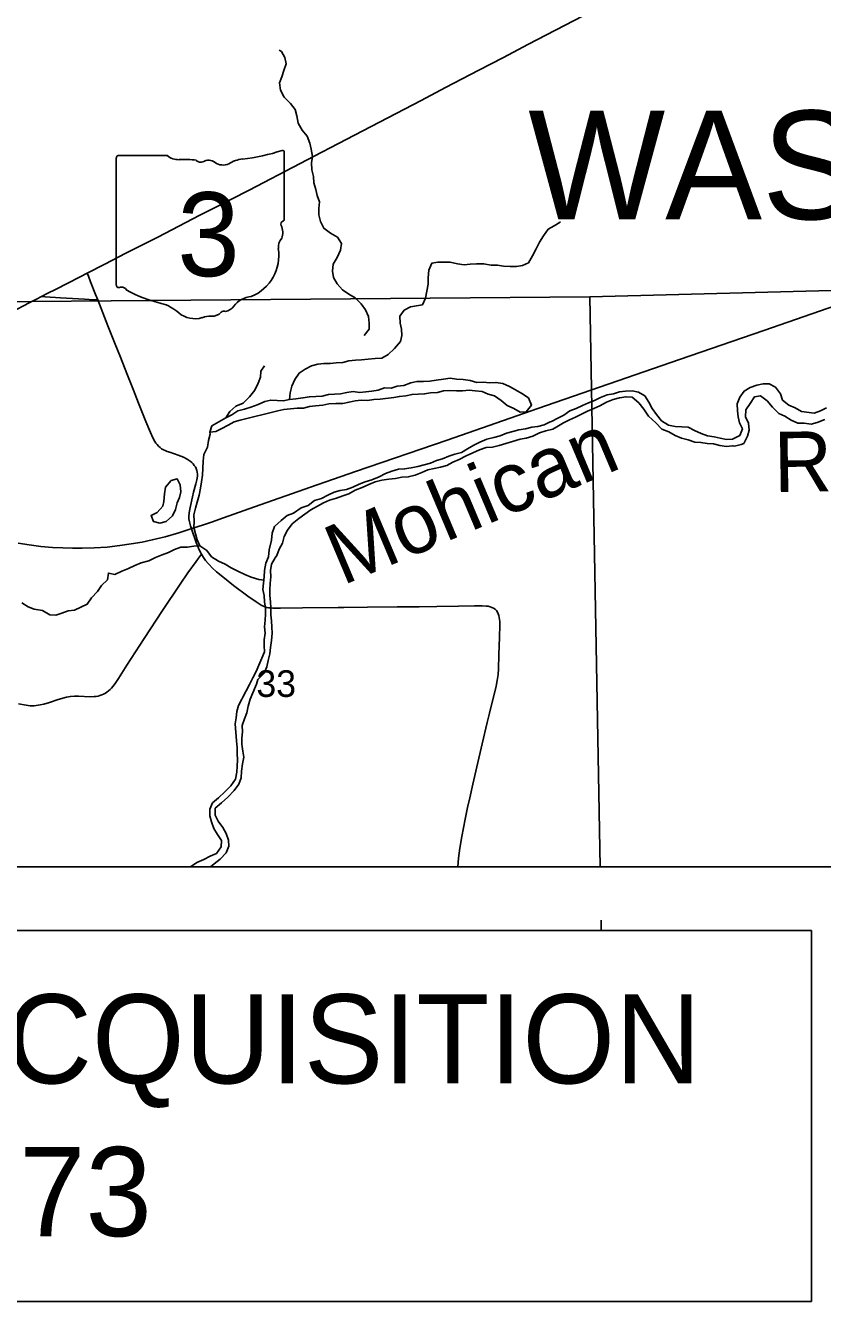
# Model space of a CAD drawing. Extents: x 0 to 34, y 0 to 22.
# Drawn here: x 6.214 to 7.465, y 16.167 to 18.172 of the extents above; entities that cross this region are included whole.
import ezdxf

# ---------------------------------------------------------------- set-up
doc = ezdxf.new("R2010")
doc.units = 0
for name, color, linetype in [('GM_X_County_Road', 7, 'Continuous'), ('GM_X_County_Road_Text', 7, 'Continuous'), ('GM_X_County_Text', 7, 'Continuous'), ('GM_X_Major_River', 7, 'Continuous'), ('GM_X_Major_River_Text', 7, 'Continuous'), ('GM_X_Minor_River_Text', 7, 'Continuous'), ('GM_X_State_Location', 7, 'Continuous'), ('GM_X_State_Route', 7, 'Continuous'), ('GM_X_State_Shield', 7, 'Continuous'), ('GM_X_Township_Road', 7, 'Continuous'), ('GM_X_Unincorporated_Location', 7, 'Continuous'), ('SH_Text', 7, 'Continuous')]:
    doc.layers.add(name, color=color, linetype=linetype)

msp = doc.modelspace()

# ---------------------------------------------------------------- linework, layer by layer
at = {"layer": 'GM_X_County_Road'}
for p, q in [((6.3562, 17.9642), (6.3562, 17.764)), ((6.436, 17.9676), (6.3588, 17.9676)), ((6.6199, 17.8679), (6.6199, 17.9726)), ((6.6199, 17.8679), (6.6199, 17.8679))]:
    msp.add_line(p, q, dxfattribs=at)
msp.add_lwpolyline([(6.1918, 17.7219), (6.2195, 17.7361), (6.2309, 17.742), (6.2388, 17.7461), (6.2489, 17.7513), (6.2608, 17.7575), (6.2995, 17.7773), (6.3105, 17.783), (6.3381, 17.7972), (6.3713, 17.8141), (6.4212, 17.8395), (6.4874, 17.8738), (6.5123, 17.8866), (6.5372, 17.8991), (6.5648, 17.9134), (6.6448, 17.955), (6.6668, 17.9665), (6.7053, 17.9867), (6.7301, 17.9997), (6.8348, 18.0543), (6.8733, 18.0745), (6.9256, 18.102), (6.9642, 18.122), (7.0028, 18.1422), (7.0896, 18.1872)], dxfattribs=at)
for centre, radius, start, end in [((6.3593, 17.9646), 0.00305, 98.1301, 188.1301), ((6.4544, 17.9908), 0.0296, 231.6195, 271.1119), ((6.4643, 17.8553), 0.1064, 80.4867, 94.9883), ((6.5616, 17.9065), 0.0563, 97.3462, 120.7689), ((6.526, 18.2404), 0.2796, 275.8445, 288.9065), ((6.617, 17.973), 0.00294, 351.8621, 97.738), ((6.4884, 17.9656), 0.00855, 219.7921, 297.1024), ((6.5009, 17.9425), 0.0178, 54.4667, 119.1411), ((6.5239, 17.9742), 0.0214, 233.8562, 294.8282), ((6.6192, 17.8602), 0.00454, 107.944, 210.337), ((6.6168, 17.8675), 0.00314, 289.6038, 7.7341), ((6.5903, 17.847), 0.0273, 340.033, 23.6496), ((6.5416, 17.8108), 0.0699, 292.3089, 8.9858), ((6.6304, 17.8241), 0.0198, 136.8065, 186.9296), ((6.3593, 17.7636), 0.00308, 171.9584, 258.3066), ((6.3597, 17.7841), 0.0235, 267.339, 280.6039), ((6.3646, 17.7525), 0.00848, 29.7484, 93.2717), ((6.4716, 17.9323), 0.2019, 240.4129, 257.1985), ((6.5711, 17.7079), 0.0383, 94.4031, 142.5768), ((6.4114, 17.6741), 0.0632, 47.1842, 75.836), ((6.5058, 17.7365), 0.0214, 268.777, 315.5493), ((6.5252, 17.7171), 0.00601, 65.7517, 132.6484), ((6.5226, 17.7446), 0.0226, 282.8732, 323.2771), ((6.4797, 17.7515), 0.0401, 230.7004, 286.2918), ((6.5029, 17.6823), 0.0329, 85.6951, 111.2099)]:
    msp.add_arc(centre, radius, start, end, dxfattribs=at)
at = {"layer": 'GM_X_County_Road_Text'}
for points in [[(6.7453, 17.685), (6.7533, 17.6948), (6.7534, 17.7042), (6.7524, 17.7149), (6.7475, 17.7252), (6.7408, 17.7347), (6.7314, 17.7443), (6.7216, 17.75), (6.7114, 17.7566), (6.7031, 17.7661), (6.6972, 17.776), (6.6957, 17.7859), (6.6966, 17.7969), (6.7031, 17.8075), (6.7085, 17.8192), (6.7097, 17.8294), (6.7037, 17.8393), (6.6924, 17.8459), (6.6823, 17.8535), (6.6767, 17.8642), (6.6741, 17.8745), (6.6742, 17.8847), (6.6754, 17.8949), (6.6717, 17.9048), (6.6695, 17.9143), (6.6662, 17.9246), (6.6659, 17.9348), (6.6633, 17.9451), (6.663, 17.9561), (6.6642, 17.966), (6.6624, 17.9777), (6.6602, 17.9872), (6.6558, 17.9979), (6.6479, 18.0078), (6.6416, 18.0185), (6.6398, 18.0299), (6.6372, 18.0398), (6.6297, 18.0493), (6.6199, 18.0593), (6.6143, 18.0703), (6.6125, 18.0817), (6.616, 18.0915), (6.6191, 18.1014), (6.623, 18.112), (6.6208, 18.1218), (6.6156, 18.1314), (6.6118, 18.1333)], [(6.6281, 17.5844), (6.6293, 17.595), (6.6321, 17.6052), (6.6367, 17.6158), (6.6432, 17.626), (6.6528, 17.632), (6.6626, 17.6372), (6.6725, 17.6397), (6.682, 17.6412), (6.6919, 17.6411), (6.7017, 17.6418), (6.712, 17.6424), (6.7215, 17.6454), (6.7317, 17.6464), (6.7412, 17.6467), (6.7518, 17.6478), (6.7628, 17.6488), (6.7734, 17.6495), (6.783, 17.6554), (6.7933, 17.6648), (6.8028, 17.6754), (6.8048, 17.6852), (6.8041, 17.6951), (6.8023, 17.7046), (6.8016, 17.7152), (6.8085, 17.725), (6.8181, 17.7302), (6.837, 17.7331), (6.8421, 17.7436), (6.8437, 17.7546), (6.846, 17.7656), (6.8461, 17.7758), (6.8473, 17.7876), (6.8516, 17.7985), (6.8611, 17.8), (6.871, 17.8003), (6.8808, 17.8002), (6.8922, 17.7978), (6.9024, 17.7962), (6.9119, 17.7972), (6.9217, 17.7975), (6.9331, 17.7978), (6.9452, 17.7954), (6.9547, 17.7953), (6.9645, 17.7941), (6.9747, 17.7933), (6.9846, 17.7935), (6.9941, 17.795), (7.0036, 17.7994), (7.0101, 17.81), (7.0159, 17.8209), (7.0209, 17.8315), (7.0271, 17.8417), (7.0344, 17.8519), (7.0439, 17.8571), (7.0534, 17.8631), (7.0519, 17.8627)], [(6.5282, 17.5557), (6.5343, 17.5655), (6.5439, 17.5742), (6.5553, 17.5786), (6.5656, 17.5888), (6.5736, 17.5989), (6.579, 17.6099), (6.5829, 17.6197), (6.583, 17.6292), (6.5891, 17.6375)], [(6.4875, 17.3544), (6.483, 17.3639), (6.4804, 17.3734), (6.4782, 17.3836), (6.4783, 17.3931), (6.478, 17.4034), (6.4804, 17.4136), (6.4831, 17.4234), (6.4862, 17.4344), (6.4882, 17.4454), (6.4898, 17.4552), (6.4914, 17.4654), (6.4919, 17.4768), (6.4927, 17.4878), (6.4936, 17.498), (6.4994, 17.5093), (6.501, 17.52), (6.5037, 17.5298), (6.503, 17.5332)], [(6.2078, 17.2651), (6.2176, 17.2586), (6.2274, 17.2551), (6.2403, 17.2531), (6.2516, 17.2461), (6.261, 17.2457), (6.2705, 17.2486), (6.2808, 17.2523), (6.2907, 17.2537), (6.3006, 17.2582), (6.3105, 17.263), (6.3174, 17.2728), (6.3265, 17.2826), (6.3327, 17.2924), (6.3422, 17.3011), (6.3438, 17.3117), (6.3541, 17.3097), (6.3651, 17.3149), (6.3754, 17.319), (6.3853, 17.3234), (6.3955, 17.3279), (6.4073, 17.3312), (6.4176, 17.3364), (6.4282, 17.3405), (6.4381, 17.3442), (6.4476, 17.3486), (6.4575, 17.3527), (6.4677, 17.3523), (6.478, 17.3541), (6.4875, 17.3544), (6.4984, 17.347), (6.5055, 17.3375), (6.5165, 17.3306), (6.527, 17.3256), (6.5368, 17.3202), (6.547, 17.3148), (6.558, 17.3097), (6.5682, 17.3055), (6.5803, 17.3016), (6.5882, 17.3007)]]:
    msp.add_lwpolyline(points, dxfattribs=at)
at = {"layer": 'GM_X_County_Text'}
msp.add_lwpolyline([(6.202, 17.3585), (6.2191, 17.356), (6.2374, 17.3536), (6.2559, 17.3519), (6.2721, 17.3512), (6.2873, 17.3507), (6.3024, 17.3508), (6.3216, 17.3513), (6.3419, 17.3527), (6.3619, 17.355), (6.3793, 17.3575), (6.3967, 17.3605), (6.4127, 17.3639), (6.4327, 17.3687), (6.4546, 17.3751), (6.4748, 17.3816), (6.493, 17.3873), (6.5055, 17.3919), (6.5244, 17.3984), (6.5733, 17.4156), (6.6611, 17.4466), (6.7321, 17.4713), (6.8757, 17.5205), (7.0185, 17.5701), (7.2408, 17.6471), (7.373, 17.6931), (7.8394, 17.8546)], dxfattribs=at)
at = {"layer": 'GM_X_Minor_River_Text'}
for points in [[(6.7919, 17.5875), (6.801, 17.5893), (6.8108, 17.59), (6.8207, 17.5925), (6.8302, 17.5928), (6.8404, 17.5931), (6.8499, 17.5949), (6.8605, 17.5952), (6.87, 17.5981), (6.8803, 17.5984), (6.8905, 17.5983), (6.9, 17.5979), (6.9102, 17.5989), (6.9201, 17.5981), (6.9307, 17.5968), (6.9405, 17.593), (6.9503, 17.5902), (6.9605, 17.5829), (6.9703, 17.5752), (6.9805, 17.5702), (6.9907, 17.5648), (7.0001, 17.5651), (7.0082, 17.5757), (7.0034, 17.5871), (6.9932, 17.594), (6.9834, 17.5998), (6.9736, 17.6048), (6.9634, 17.6094), (6.9524, 17.6114), (6.9425, 17.6108), (6.9327, 17.6116), (6.9224, 17.6113), (6.9119, 17.6141), (6.9009, 17.6157), (6.8907, 17.6165), (6.8804, 17.6178), (6.8702, 17.6163), (6.8588, 17.6146), (6.8489, 17.6135), (6.8387, 17.6125), (6.8281, 17.6126), (6.8186, 17.6104), (6.8079, 17.6067), (6.7973, 17.6052), (6.7878, 17.6023), (6.7776, 17.6028), (6.7677, 17.5991), (6.7575, 17.5976), (6.748, 17.5966), (6.7381, 17.5955), (6.7283, 17.5968), (6.7184, 17.5953), (6.7085, 17.5935), (6.6896, 17.5922), (6.6793, 17.5896), (6.6698, 17.5893), (6.6596, 17.5887), (6.6493, 17.5869), (6.638, 17.5855), (6.6281, 17.5844), (6.6182, 17.5826), (6.6088, 17.5827), (6.5989, 17.5835), (6.5894, 17.5813), (6.5788, 17.5765), (6.5677, 17.5724), (6.5575, 17.5691), (6.5472, 17.5666), (6.5377, 17.5606), (6.5282, 17.5557), (6.5061, 17.543), (6.503, 17.5332), (6.5125, 17.5343), (6.522, 17.5387), (6.5319, 17.5443), (6.5414, 17.5495), (6.5509, 17.5521)], [(6.5509, 17.5521), (6.6098, 17.5664), (6.6193, 17.5686), (6.6299, 17.5696), (6.6401, 17.571), (6.65, 17.5709), (6.6595, 17.5735), (6.669, 17.5746), (6.6807, 17.5756), (6.6902, 17.5774), (6.7008, 17.5784), (6.7118, 17.5783), (6.7217, 17.5805), (6.7312, 17.5823), (6.741, 17.5834), (6.7509, 17.5829), (6.7608, 17.5843), (6.7706, 17.585), (6.7919, 17.5875)], [(6.4557, 17.4307), (6.4578, 17.4392), (6.4564, 17.4502), (6.452, 17.4597), (6.4425, 17.4572), (6.4333, 17.4466), (6.4317, 17.4364), (6.4309, 17.4241)], [(6.4309, 17.4241), (6.4292, 17.4171), (6.4204, 17.4069), (6.4109, 17.4024), (6.4146, 17.3929), (6.4245, 17.3902), (6.4347, 17.3928), (6.4447, 17.4018), (6.4493, 17.4116), (6.452, 17.4222), (6.4557, 17.4307)]]:
    msp.add_lwpolyline(points, dxfattribs=at)
at = {"layer": 'GM_X_State_Route'}
msp.add_line((7.1178, 16.7504), (7.1176, 16.7664), dxfattribs=at)
for points in [[(7.1161, 16.8504), (7.0999, 17.7456), (8.0984, 17.7721), (8.1109, 16.7736), (7.5483, 16.7695)], [(6.0967, 17.7375), (7.0999, 17.7456), (7.1161, 16.8504)]]:
    msp.add_lwpolyline(points, dxfattribs=at)
at = {"layer": 'GM_X_State_Shield'}
for points in [[(7.4717, 17.5715), (7.4622, 17.5666), (7.4523, 17.5629), (7.4326, 17.5654), (7.4224, 17.5715), (7.4126, 17.5754), (7.4024, 17.5835), (7.3995, 17.5934), (7.3916, 17.6037), (7.3814, 17.6091), (7.372, 17.6088), (7.3625, 17.607), (7.3518, 17.6033), (7.3423, 17.5977), (7.3354, 17.5879), (7.3315, 17.5777), (7.3318, 17.5667), (7.3329, 17.5572), (7.3351, 17.5477), (7.3395, 17.5382), (7.3353, 17.528), (7.3242, 17.522), (7.3148, 17.5217), (7.3049, 17.5237), (7.2951, 17.526), (7.2849, 17.5273), (7.275, 17.5312), (7.2645, 17.5358), (7.2543, 17.5408), (7.2444, 17.5417), (7.2342, 17.5421), (7.2236, 17.5441), (7.2123, 17.5511), (7.2048, 17.561), (7.198, 17.5705), (7.1924, 17.5804), (7.1861, 17.59), (7.1763, 17.5958), (7.1664, 17.5981), (7.1562, 17.5975), (7.1467, 17.5964), (7.1372, 17.5935), (7.1273, 17.592), (7.1167, 17.5876), (7.1072, 17.5831), (7.0977, 17.5794), (7.0882, 17.5749), (7.0786, 17.5701), (7.0688, 17.5664), (7.0592, 17.5596), (7.0497, 17.5552), (7.0398, 17.55)], [(7.0481, 17.5415), (7.0584, 17.5479), (7.0679, 17.5524), (7.0774, 17.5565), (7.0964, 17.5661), (7.1063, 17.5702), (7.1158, 17.5743), (7.1261, 17.5803), (7.1364, 17.5847), (7.1463, 17.5869), (7.1569, 17.5887), (7.1667, 17.5883), (7.1769, 17.5791), (7.1848, 17.5695), (7.1919, 17.5581), (7.2035, 17.5477), (7.2129, 17.5378), (7.2239, 17.5335), (7.2341, 17.5281), (7.2439, 17.5238), (7.2545, 17.5211), (7.2651, 17.5172), (7.2745, 17.5171), (7.2844, 17.5151), (7.2942, 17.5147), (7.3041, 17.5123), (7.3147, 17.5107), (7.3242, 17.5114), (7.3253, 17.5117)], [(7.3374, 17.5139), (7.3416, 17.5154), (7.3478, 17.5267), (7.3501, 17.5365), (7.3491, 17.5475), (7.3442, 17.5571), (7.3451, 17.5681), (7.352, 17.5782), (7.3585, 17.5884), (7.368, 17.5902), (7.3786, 17.5825)], [(7.3786, 17.5825), (7.3868, 17.5722), (7.3966, 17.5627), (7.4064, 17.5584), (7.4162, 17.5522), (7.4268, 17.5472), (7.4366, 17.5471), (7.4476, 17.5455), (7.4571, 17.5485), (7.4693, 17.5529)], [(7.0398, 17.55), (7.0375, 17.5496), (7.028, 17.5448), (7.0185, 17.5422), (7.009, 17.5408), (6.9988, 17.5382), (6.9885, 17.5368), (6.979, 17.5342), (6.9692, 17.5316), (6.9589, 17.5276), (6.9494, 17.525), (6.9384, 17.5221), (6.9274, 17.5176), (6.9175, 17.5128), (6.9079, 17.5072), (6.8984, 17.5012), (6.8878, 17.4986), (6.8783, 17.4953), (6.8688, 17.4912), (6.8593, 17.4886), (6.8498, 17.4846), (6.8399, 17.482), (6.8296, 17.4794), (6.8194, 17.4772), (6.8091, 17.4754), (6.7993, 17.4748), (6.789, 17.4718), (6.7791, 17.4681), (6.7689, 17.4629), (6.7578, 17.4585), (6.7472, 17.4552), (6.7377, 17.4514), (6.7278, 17.4466), (6.7175, 17.4433), (6.7076, 17.4415), (6.6982, 17.4389), (6.6886, 17.4344), (6.6784, 17.4288), (6.6677, 17.4259), (6.6574, 17.418), (6.6464, 17.4143), (6.6346, 17.4057), (6.6247, 17.402), (6.6152, 17.3945), (6.6048, 17.3848), (6.601, 17.3746), (6.6001, 17.3636)], [(6.6083, 17.3392), (6.6121, 17.3491), (6.6171, 17.3589), (6.6199, 17.3691), (6.6249, 17.3793), (6.6325, 17.3891), (6.6429, 17.3977), (6.6524, 17.4041), (6.6619, 17.4112), (6.6722, 17.4168), (6.6817, 17.422), (6.6912, 17.4261), (6.7022, 17.4294), (6.7121, 17.4331), (6.7216, 17.436), (6.7315, 17.442), (6.7422, 17.4461), (6.7528, 17.4509), (6.7627, 17.455), (6.773, 17.4576), (6.784, 17.4594), (6.7946, 17.4604), (6.8045, 17.4622), (6.8147, 17.4629), (6.8257, 17.4654), (6.836, 17.4699), (6.8455, 17.474), (6.8554, 17.4758), (6.8656, 17.4783), (6.8755, 17.4805), (6.885, 17.4861), (6.8949, 17.4902), (6.9056, 17.4958), (6.9162, 17.5006), (6.9265, 17.5055), (6.9371, 17.5088), (6.947, 17.5095), (6.9576, 17.5124), (6.9679, 17.5153), (6.9785, 17.5187), (6.9903, 17.522), (6.9998, 17.5238), (7.0104, 17.5271), (7.0207, 17.5319), (7.031, 17.5353), (7.042, 17.5378), (7.0481, 17.5415)], [(7.3253, 17.5117), (7.3272, 17.5113), (7.3374, 17.5139)], [(6.6001, 17.3636), (6.5962, 17.3484), (6.5954, 17.3374), (6.5911, 17.3272), (6.5891, 17.3159), (6.5883, 17.306), (6.5874, 17.2958), (6.5866, 17.286), (6.5884, 17.2765), (6.5891, 17.2666), (6.5905, 17.2567), (6.5904, 17.2472), (6.59, 17.2378), (6.5891, 17.2275), (6.5898, 17.2173), (6.5886, 17.2071), (6.5885, 17.1976), (6.5892, 17.1881), (6.5849, 17.1783), (6.5803, 17.1673), (6.576, 17.1571), (6.5707, 17.1473), (6.5656, 17.1367), (6.5603, 17.1269), (6.5547, 17.1166)], [(6.5786, 17.1446), (6.5882, 17.1543), (6.5928, 17.1645), (6.5948, 17.1744), (6.5971, 17.185), (6.5983, 17.1948), (6.5999, 17.2058), (6.6012, 17.2172), (6.6005, 17.2267), (6.6002, 17.2369), (6.5988, 17.2464), (6.5989, 17.257), (6.5982, 17.2665), (6.5975, 17.2764), (6.5976, 17.2859), (6.598, 17.2953), (6.5989, 17.3059), (6.5986, 17.3158), (6.6002, 17.3256), (6.6056, 17.3358), (6.6083, 17.3392)], [(6.5746, 17.1333), (6.5763, 17.1374), (6.5786, 17.1446)], [(6.5042, 16.8504), (6.5099, 16.8551), (6.5194, 16.8622), (6.5286, 16.8724), (6.5332, 16.8826), (6.5322, 16.8924), (6.5285, 16.9027), (6.5236, 16.9122), (6.5161, 16.9218), (6.5116, 16.9313), (6.5117, 16.9423), (6.5213, 16.9509), (6.5312, 16.9599), (6.5415, 16.9701), (6.5484, 16.9803), (6.5523, 16.9901), (6.5531, 17.0007), (6.5544, 17.0121), (6.5567, 17.0227), (6.5549, 17.0322), (6.5535, 17.0428), (6.5532, 17.0523), (6.5544, 17.0625), (6.5541, 17.0724), (6.5576, 17.0826), (6.5611, 17.0924), (6.5631, 17.1026), (6.5662, 17.1136), (6.5746, 17.1333)], [(6.5547, 17.1166), (6.5533, 17.1137), (6.5479, 17.1039), (6.5456, 17.0941), (6.5447, 17.0842), (6.543, 17.0751)], [(6.543, 17.0751), (6.5452, 17.0482), (6.5462, 17.0375), (6.5458, 17.0281), (6.5465, 17.0186), (6.546, 17.0083), (6.5455, 16.9989), (6.5436, 16.9879), (6.5363, 16.9773), (6.5267, 16.968), (6.5168, 16.9589), (6.5072, 16.9507), (6.503, 16.9409), (6.5033, 16.9306), (6.5055, 16.9207), (6.5096, 16.9105), (6.5152, 16.9009), (6.5212, 16.8914), (6.5211, 16.8815), (6.5134, 16.8714), (6.5035, 16.8669), (6.4936, 16.8617), (6.4826, 16.8569), (6.4725, 16.8504)]]:
    msp.add_lwpolyline(points, dxfattribs=at)
at = {"layer": 'GM_X_Township_Road'}
for points in [[(6.327, 17.7408), (6.3236, 17.7492), (6.3157, 17.7695), (6.3124, 17.7782), (6.3105, 17.783)], [(6.327, 17.7408), (6.3216, 17.7411), (6.306, 17.742), (6.2876, 17.7431), (6.2683, 17.7443), (6.2446, 17.7457), (6.2388, 17.7461)], [(6.4901, 17.3414), (6.4881, 17.3449), (6.4853, 17.3507), (6.4836, 17.355), (6.4822, 17.3581), (6.4799, 17.3645), (6.4758, 17.3765), (6.4729, 17.3861), (6.4712, 17.392), (6.4703, 17.3968), (6.4701, 17.4016), (6.4712, 17.4096), (6.4721, 17.4148), (6.4759, 17.4313), (6.4777, 17.4389), (6.4812, 17.4521), (6.4827, 17.4581), (6.4835, 17.4641), (6.4835, 17.4671), (6.4833, 17.4701), (6.4826, 17.473), (6.4817, 17.4758), (6.4804, 17.4785), (6.4787, 17.481), (6.4768, 17.4833), (6.4747, 17.4854), (6.4724, 17.4874), (6.4673, 17.4907), (6.4619, 17.4936), (6.4533, 17.4972), (6.4476, 17.4993), (6.4447, 17.5002), (6.4419, 17.501), (6.436, 17.503), (6.433, 17.5041), (6.4302, 17.5055), (6.4274, 17.5071), (6.4249, 17.509), (6.4225, 17.5111), (6.4203, 17.5135), (6.4184, 17.516), (6.4167, 17.5186), (6.4137, 17.5242), (6.4098, 17.5327), (6.4027, 17.55), (6.3912, 17.5789), (6.3832, 17.5991), (6.3729, 17.6251), (6.3627, 17.651), (6.3546, 17.6712), (6.3431, 17.7001), (6.327, 17.7408)], [(6.2026, 17.1065), (6.2148, 17.104), (6.221, 17.1032), (6.2272, 17.1032), (6.2303, 17.1035), (6.2364, 17.1045), (6.2425, 17.1059), (6.2514, 17.1085), (6.2632, 17.1124), (6.2721, 17.1153), (6.2781, 17.1168), (6.2842, 17.1179), (6.2903, 17.1184), (6.2966, 17.1184), (6.3152, 17.1175), (6.3214, 17.1176), (6.3245, 17.1179), (6.3275, 17.1184), (6.3305, 17.1193), (6.3334, 17.1203), (6.3363, 17.1216), (6.339, 17.1231), (6.3415, 17.1248), (6.344, 17.1267), (6.3463, 17.1288), (6.3485, 17.131), (6.3505, 17.1334), (6.3543, 17.1383), (6.3595, 17.146), (6.3727, 17.1671), (6.3998, 17.2089), (6.429, 17.2529), (6.4565, 17.2943), (6.4688, 17.3123), (6.4814, 17.3301), (6.4851, 17.335), (6.4901, 17.3414)], [(6.5018, 17.3253), (6.5004, 17.3268), (6.4964, 17.3316), (6.4932, 17.3361), (6.4901, 17.3414)], [(6.7047, 17.2575), (6.6485, 17.257), (6.6143, 17.2568), (6.6018, 17.2567), (6.5986, 17.2569), (6.5955, 17.2572), (6.5924, 17.2579), (6.5894, 17.2588), (6.5837, 17.2615), (6.5757, 17.2665), (6.5629, 17.2755), (6.5405, 17.2922), (6.5233, 17.3056), (6.5137, 17.3136), (6.5068, 17.32), (6.5018, 17.3253)], [(6.8926, 16.8504), (6.8938, 16.864), (6.8958, 16.8794), (6.8987, 16.8979), (6.9041, 16.9253), (6.908, 16.9436), (6.9114, 16.9587), (6.9163, 16.9799), (6.9226, 17.0072), (6.9311, 17.0435), (6.9387, 17.0768), (6.9422, 17.0919), (6.9526, 17.1341), (6.9545, 17.1432), (6.9558, 17.1523), (6.9565, 17.1615), (6.9572, 17.1832), (6.958, 17.2112), (6.9586, 17.2298), (6.9584, 17.2359), (6.9582, 17.239), (6.9578, 17.242), (6.9571, 17.245), (6.9561, 17.2479), (6.9548, 17.2505), (6.9531, 17.2529), (6.9511, 17.2549), (6.9487, 17.2566), (6.946, 17.2579), (6.9432, 17.2589), (6.9403, 17.2596), (6.9373, 17.26), (6.9311, 17.2604), (6.9188, 17.2604), (6.8939, 17.26), (6.8597, 17.2592), (6.8318, 17.2589), (6.7976, 17.2586), (6.751, 17.2581), (6.7137, 17.2576), (6.7047, 17.2575)]]:
    msp.add_lwpolyline(points, dxfattribs=at)
at = {"layer": 'SH_Text'}
for p, q in [((5.4199, 16.8504), (7.5483, 16.8504)), ((5.5199, 16.7504), (7.4483, 16.7504)), ((7.4483, 16.1674), (7.4483, 16.7504)), ((5.5199, 16.1674), (7.4483, 16.1674))]:
    msp.add_line(p, q, dxfattribs=at)

# ---------------------------------------------------------------- texts
at = {"layer": 'GM_X_County_Road'}
msp.add_text('3', height=0.1318, dxfattribs=at).set_placement((6.452, 17.7782))
at = {"layer": 'GM_X_Major_River'}
msp.add_text('WASHINGTON', height=0.17045, rotation=0, dxfattribs=at).set_placement((7.0032, 17.8677))
at = {"layer": 'GM_X_Major_River_Text'}
for s in ['s', 'r']:
    msp.add_text(s, height=0.000189, dxfattribs=at).set_placement((6.4851, 17.8508))
msp.add_text('3', height=0.000189, rotation=0, dxfattribs=at).set_placement((6.4566, 17.837))
at = {"layer": 'GM_X_State_Location'}
msp.add_text('33', height=0.04186, rotation=0, dxfattribs=at).set_placement((6.5762, 17.1172))
at = {"layer": 'GM_X_Unincorporated_Location'}
for s, rotation, p in [('River', 0.8813, (7.3896, 17.4388)), ('Mohican', 22.8818, (6.7112, 17.2917))]:
    msp.add_text(s, height=0.09471, rotation=rotation, dxfattribs=at).set_placement(p)
at = {"layer": 'SH_Text'}
for s, p in [('END ACQUISITION', (5.6106, 16.51)), ('SLM 0.73', (5.6106, 16.27))]:
    msp.add_text(s, height=0.14, dxfattribs=at).set_placement(p)

doc.saveas('drawing.dxf')
